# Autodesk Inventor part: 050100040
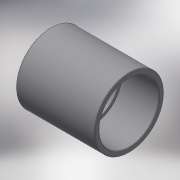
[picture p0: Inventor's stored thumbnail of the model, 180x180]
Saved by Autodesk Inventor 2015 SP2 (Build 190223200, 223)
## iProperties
Created: 2017-10
Part Number: 050100040
Material: Generic
Description: PLASSON SOCKET PVC 40 - CEMENT
Document SubType Name: Modeling
Designer: KIM
Density: 1 g/cm^3
Appearance: Default
Author: KIM
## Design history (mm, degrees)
derived "050100.ipt"
feature "Solid1::050100.ipt"
tag "TaggingFeature1"
body "Solid1"
other parameters: "d0" = 56, "d1" = 48, "d2" = 26, "d3" = 4, "d5" = 36, "d7" = 0.4, "E_" = 48, "H_" = 56, "l_" = 26, "Z_" = 4
